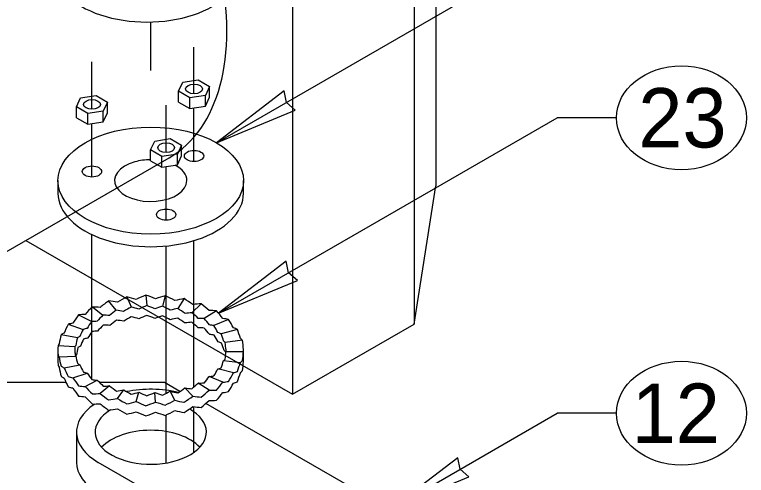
# Model space of a CAD drawing. Extents: x 99862 to 104211, y 98939 to 105076.
# Drawn here: x 101481.1 to 101678.3, y 101634.5 to 101758.7 of the extents above; entities that cross this region are included whole.
import ezdxf

# ---------------------------------------------------------------- set-up
doc = ezdxf.new("R2010")
doc.units = 0
for name, color, linetype in [('Level 11', 7, 'Continuous'), ('Level 12', 7, 'Continuous'), ('Level 15', 7, 'Continuous'), ('Level 2', 7, 'Continuous'), ('Level 20', 7, 'Continuous'), ('Level 24', 7, 'Continuous'), ('Level 26', 7, 'Continuous')]:
    doc.layers.add(name, color=color, linetype=linetype)

msp = doc.modelspace()

# ---------------------------------------------------------------- linework, layer by layer
at = {"layer": 'Level 11'}
for p, q in [((101525.26, 101738.07), (101526.38, 101740.49)), ((101526.38, 101740.49), (101530.56, 101741.13)), ((101530.56, 101741.13), (101533.62, 101739.37)), ((101525.26, 101735.16), (101525.26, 101738.07)), ((101528.32, 101736.31), (101525.26, 101738.07)), ((101533.62, 101739.37), (101532.5, 101736.95)), ((101533.62, 101736.46), (101533.62, 101739.37)), ((101497.75, 101733.87), (101498.87, 101736.28)), ((101498.87, 101736.28), (101503.05, 101736.93)), ((101503.05, 101736.93), (101506.11, 101735.16)), ((101532.5, 101736.95), (101528.32, 101736.31)), ((101528.32, 101733.4), (101528.32, 101736.31)), ((101532.5, 101734.04), (101532.5, 101736.95)), ((101532.5, 101734.04), (101533.62, 101736.46)), ((101497.75, 101730.96), (101497.75, 101733.87)), ((101500.81, 101732.1), (101497.75, 101733.87)), ((101506.11, 101735.16), (101504.99, 101732.75)), ((101506.11, 101732.25), (101506.11, 101735.16)), ((101525.26, 101735.16), (101528.32, 101733.4)), ((101528.32, 101733.4), (101532.5, 101734.04)), ((101504.99, 101732.75), (101500.81, 101732.1)), ((101500.81, 101729.19), (101500.81, 101732.1)), ((101504.99, 101729.84), (101504.99, 101732.75)), ((101504.99, 101729.84), (101506.11, 101732.25)), ((101497.75, 101730.96), (101500.81, 101729.19)), ((101500.81, 101729.19), (101504.99, 101729.84)), ((101517.73, 101722.26), (101518.86, 101724.67)), ((101518.86, 101724.67), (101523.04, 101725.32)), ((101523.04, 101725.32), (101526.1, 101723.55)), ((101517.73, 101719.35), (101517.73, 101722.26)), ((101520.8, 101720.49), (101517.73, 101722.26)), ((101526.1, 101723.55), (101524.98, 101721.14)), ((101526.1, 101720.64), (101526.1, 101723.55)), ((101524.98, 101721.14), (101520.8, 101720.49)), ((101520.8, 101717.58), (101520.8, 101720.49)), ((101524.98, 101718.23), (101524.98, 101721.14)), ((101524.98, 101718.23), (101526.1, 101720.64)), ((101517.73, 101719.35), (101520.8, 101717.58)), ((101520.8, 101717.58), (101524.98, 101718.23)), ((101492.77, 101713.99), (101492.77, 101710.59)), ((101542.77, 101710.59), (101542.77, 101713.99))]:
    msp.add_line(p, q, dxfattribs=at)
for centre, major_axis in [((101529.44, 101738.72), (2.27, 0)), ((101501.93, 101734.52), (2.27, 0)), ((101517.77, 101713.99), (-25, 0)), ((101521.92, 101722.9), (2.27, 0)), ((101529.44, 101720.64), (-2.6, 0)), ((101501.93, 101716.44), (-2.6, 0)), ((101521.92, 101704.83), (-2.6, 0))]:
    msp.add_ellipse(centre, major_axis=major_axis, ratio=0.57735, dxfattribs=at)
for centre, major_axis, start_param, end_param in [((101517.77, 101713.99), (9.74, 0), 2.024427, 6.283185), ((101517.77, 101713.99), (9.74, 0), 1.57464, 2.024427), ((101517.77, 101713.99), (9.74, 0), 0, 0.827732), ((101517.77, 101710.59), (-25, 0), 0, 3.141593)]:
    msp.add_ellipse(centre, major_axis=major_axis, ratio=0.57735, start_param=start_param, end_param=end_param, dxfattribs=at)
at = {"layer": 'Level 12'}
for p, q in [((101618.94, 101604.1), (101532.64, 101653.92)), ((101497.77, 101646.17), (101497.77, 101638.01)), ((101604.42, 101579.82), (101503.63, 101638.01))]:
    msp.add_line(p, q, dxfattribs=at)
for centre, major_axis, start_param, end_param in [((101517.77, 101646.17), (-20, 0), 4.329676, 5.04454), ((101517.77, 101646.17), (-20, 0), 5.567806, 7.068583), ((101517.77, 101646.17), (-15, 0), 5.520663, 10.229056), ((101517.77, 101638.01), (15, 0), 0.490883, 2.65071), ((101517.77, 101638.01), (20, 0), 3.141593, 3.926991)]:
    msp.add_ellipse(centre, major_axis=major_axis, ratio=0.57735, start_param=start_param, end_param=end_param, dxfattribs=at)
at = {"layer": 'Level 15'}
for p, q in [((101535.45, 101724.2), (101627.26, 101777.2)), ((101517.77, 101743.71), (101517.77, 101756.75)), ((101529.37, 101737.41), (101529.37, 101749.96)), ((101501.93, 101733.21), (101501.93, 101746.05)), ((101521.92, 101721.59), (101521.92, 101734.29)), ((101529.37, 101719.14), (101529.37, 101733.56)), ((101536.02, 101678.25), (101627.26, 101730.92)), ((101643.26, 101730.92), (101627.26, 101730.92)), ((101501.93, 101714.93), (101501.93, 101729.36)), ((101521.92, 101703.32), (101521.92, 101717.75)), ((101501.93, 101660.33), (101501.93, 101699.42)), ((101521.92, 101656.61), (101521.92, 101696.35)), ((101529.37, 101658.34), (101529.37, 101697.8)), ((101529.37, 101640.68), (101529.37, 101653.04)), ((101521.92, 101637.85), (101521.92, 101650.81)), ((101582.24, 101625.28), (101627.26, 101651.27)), ((101643.26, 101651.27), (101627.26, 101651.27))]:
    msp.add_line(p, q, dxfattribs=at)
for points in [[(101535.45, 101724.2), (101556.71, 101733.02), (101554.31, 101735.08), (101553.73, 101738.2)], [(101536.02, 101678.25), (101557.28, 101687.08), (101554.88, 101689.14), (101554.3, 101692.25)], [(101582.24, 101625.28), (101603.5, 101634.11), (101601.1, 101636.17), (101600.52, 101639.28)]]:
    msp.add_lwpolyline(points, close=True, dxfattribs=at)
at = {"layer": 'Level 2'}
msp.add_ellipse((101516.75, 101771.17), major_axis=(-25, 0), ratio=0.57735, start_param=0, end_param=3.141593, dxfattribs=at)
at = {"layer": 'Level 20'}
for centre in [(101660.76, 101730.92), (101660.76, 101651.27)]:
    msp.add_ellipse(centre, major_axis=(-17.5, 0), ratio=0.8, dxfattribs=at)
at = {"layer": 'Level 24'}
for p, q in [((101511.3, 101682.63), (101512.48, 101679.91)), ((101516.46, 101683.11), (101516.7, 101680.28)), ((101521.68, 101682.95), (101520.96, 101680.13)), ((101508.49, 101679.03), (101506.42, 101681.55)), ((101526.73, 101682.17), (101525.07, 101679.48)), ((101528.84, 101678.35), (101531.38, 101680.8)), ((101502.04, 101679.91), (101504.89, 101677.7)), ((101535.46, 101678.89), (101532.14, 101676.79)), ((101498.34, 101677.78), (101501.86, 101675.96)), ((101538.74, 101676.55), (101534.79, 101674.89)), ((101495.5, 101675.24), (101499.52, 101673.88)), ((101541.11, 101673.86), (101536.71, 101672.7)), ((101497.99, 101671.58), (101493.62, 101672.43)), ((101542.46, 101670.95), (101537.79, 101670.34)), ((101497.33, 101669.13), (101492.81, 101669.45)), ((101492.77, 101668.2), (101492.77, 101665.44)), ((101493.08, 101666.43), (101497.57, 101666.67)), ((101497.36, 101667.52), (101497.38, 101667.1)), ((101538.01, 101667.89), (101542.74, 101667.94)), ((101538.09, 101667.89), (101538.07, 101668.25)), ((101542.77, 101665.44), (101542.77, 101668.2)), ((101537.34, 101665.48), (101541.92, 101664.96)), ((101494.43, 101663.52), (101498.7, 101664.29)), ((101540.05, 101662.14), (101535.82, 101663.2)), ((101496.81, 101660.83), (101500.66, 101662.1)), ((101537.2, 101659.61), (101533.52, 101661.14)), ((101500.09, 101658.49), (101503.36, 101660.19)), ((101533.51, 101657.47), (101530.53, 101659.41)), ((101506.69, 101658.65), (101504.16, 101656.58)), ((101508.81, 101655.22), (101510.49, 101657.55)), ((101513.86, 101654.44), (101514.59, 101656.93)), ((101519.08, 101654.28), (101518.83, 101656.81)), ((101524.24, 101654.75), (101523.02, 101657.2)), ((101526.98, 101658.08), (101529.12, 101655.83))]:
    msp.add_line(p, q, dxfattribs=at)
for centre, major_axis, ratio, start_param, end_param in [((101517.77, 101667.71), (23.57, 14.17), 0.588004, 1.492908, 1.597627), ((101517.77, 101667.71), (-24.46, 11.73), 0.440657, 5.077658, 5.182378), ((101517.77, 101667.71), (23.99, 13.35), 0.527399, 1.337713, 1.442432), ((101517.77, 101667.71), (-24.17, 12.86), 0.497899, 4.918981, 5.0237), ((101517.77, 101667.71), (24.32, 12.32), 0.468967, 1.180574, 1.285294), ((101517.77, 101667.71), (-23.79, 13.78), 0.557438, 4.763018, 4.867737), ((101517.77, 101667.71), (23.09, 14.75), 0.650745, 1.648089, 1.752809), ((101517.77, 101667.71), (-24.67, 10.41), 0.386234, 5.240379, 5.345098), ((101517.77, 101667.71), (24.58, 11.09), 0.413044, 1.020027, 1.124747), ((101517.77, 101667.71), (-23.34, 14.49), 0.6191, 4.608118, 4.712837), ((101517.77, 101667.71), (24.76, 9.68), 0.360362, 0.8552, 0.959575), ((101517.77, 101667.71), (-22.85, 14.83), 0.683288, 4.448984, 4.554049), ((101517.77, 101667.71), (22.56, 15.04), 0.715795, 1.806331, 1.911051), ((101517.77, 101667.71), (-24.82, 8.91), 0.335596, 5.40825, 5.512969), ((101517.72, 101667.72), (-18.31, -12.12), 0.663313, 4.778515, 4.885072), ((101517.72, 101667.74), (20.54, -8.62), 0.376508, 2.084067, 2.18753), ((101517.72, 101667.71), (-18.71, -11.62), 0.598244, 4.622152, 4.729007), ((101517.72, 101667.75), (20.39, -9.75), 0.429328, 1.924562, 2.027518), ((101517.72, 101667.71), (-19.05, -10.93), 0.535491, 4.465396, 4.572456), ((101517.72, 101667.75), (20.16, -10.74), 0.484995, 1.769848, 1.872378), ((101517.72, 101667.71), (-19.34, -10.08), 0.475083, 4.306477, 4.413646), ((101517.72, 101667.75), (19.84, -11.56), 0.543025, 1.61865, 1.720863), ((101517.72, 101667.71), (-19.58, -9.08), 0.417364, 4.144071, 4.251256), ((101517.72, 101667.75), (19.43, -12.2), 0.603283, 1.46947, 1.571493), ((101517.77, 101667.71), (24.87, 8.06), 0.313871, 0.683714, 0.78878), ((101517.77, 101667.71), (-22.31, 15.05), 0.749264, 4.290148, 4.394522), ((101517.77, 101667.71), (22.09, 14.93), 0.783391, 1.973965, 2.078685), ((101517.77, 101667.71), (-24.91, 7.25), 0.290225, 5.582091, 5.686811), ((101517.72, 101667.72), (-17.89, -12.4), 0.730894, 4.937429, 5.043598), ((101517.72, 101667.74), (20.61, -7.34), 0.327453, 2.249442, 2.353465), ((101517.82, 101665.93), (-18.89, -11.29), 0.566582, 4.65521, 4.761435), ((101517.83, 101665.9), (20.47, -9.2), 0.402516, 1.905515, 2.007935), ((101517.82, 101665.93), (-19.21, -10.52), 0.50498, 4.498422, 4.604994), ((101517.83, 101665.89), (20.29, -10.27), 0.456845, 1.749535, 1.851681), ((101517.82, 101665.93), (-19.47, -9.6), 0.445851, 4.33846, 4.445308), ((101517.83, 101665.89), (20.01, -11.17), 0.51373, 1.59739, 1.699385), ((101517.82, 101665.94), (-19.68, -8.52), 0.389728, 4.174109, 4.281154), ((101517.83, 101665.89), (19.64, -11.91), 0.572873, 1.447674, 1.549653), ((101517.72, 101667.71), (-19.77, -7.94), 0.363082, 3.977435, 4.084195), ((101517.72, 101667.75), (18.96, -12.55), 0.66635, 1.317558, 1.419881), ((101517.72, 101667.71), (-19.92, -6.63), 0.315205, 3.804372, 3.911664), ((101517.72, 101667.75), (18.4, -12.84), 0.731211, 1.168256, 1.269974), ((101517.77, 101667.71), (24.94, 6.37), 0.270119, 0.507084, 0.611804), ((101517.77, 101667.71), (-21.94, 14.64), 0.818147, 4.112606, 4.217325), ((101517.77, 101667.71), (21.92, 14.08), 0.853385, 2.16914, 2.27386), ((101517.77, 101667.71), (-24.96, 5.45), 0.252109, 5.762237, 5.866957), ((101517.72, 101667.73), (-17.52, -12.37), 0.801277, 5.105481, 5.211183), ((101517.72, 101667.74), (20.62, -5.93), 0.283588, 2.42148, 2.526083), ((101517.82, 101665.92), (-18.1, -12.29), 0.696771, 4.966104, 5.071448), ((101517.83, 101665.9), (20.62, -6.65), 0.304762, 2.23369, 2.336945), ((101517.82, 101665.93), (-18.51, -11.89), 0.630481, 4.810354, 4.916165), ((101517.83, 101665.9), (20.58, -7.99), 0.351433, 2.06656, 2.169358), ((101517.82, 101665.94), (-19.85, -7.31), 0.337596, 4.00437, 4.11153), ((101517.83, 101665.89), (19.19, -12.45), 0.63428, 1.299034, 1.400798), ((101517.72, 101667.71), (-20.04, -5.26), 0.270295, 3.626269, 3.732988), ((101517.72, 101667.75), (17.89, -12.71), 0.799628, 1.006665, 1.108934), ((101517.77, 101667.71), (-24.99, 3.53), 0.223561, 5.948263, 6.052982), ((101517.72, 101667.73), (-17.45, -11.66), 0.874367, 5.304524, 5.409696), ((101517.72, 101667.73), (20.58, -4.42), 0.246838, 2.600485, 2.705657), ((101517.82, 101665.92), (-17.69, -12.44), 0.765721, 5.126739, 5.231572), ((101517.82, 101665.91), (20.61, -5.19), 0.264186, 2.407555, 2.51132), ((101517.82, 101665.93), (-19.98, -5.95), 0.29281, 3.828548, 3.936073), ((101517.83, 101665.89), (18.7, -12.68), 0.698549, 1.144423, 1.247134), ((101517.82, 101665.93), (-20.1, -4.52), 0.251785, 3.646437, 3.75321), ((101517.72, 101667.71), (-20.15, -3.75), 0.235717, 3.442095, 3.548503), ((101517.72, 101667.74), (17.65, -11.94), 0.871239, 0.815178, 0.917775), ((101517.77, 101667.71), (24.98, 4.51), 0.236491, 0.323887, 0.428607), ((101517.77, 101667.71), (-22.18, 12.98), 0.888613, 3.882951, 3.987671), ((101517.77, 101667.71), (22.99, 10.64), 0.922162, 2.476441, 2.581161), ((101517.72, 101667.74), (-18.93, -7.75), 0.945022, 5.676186, 5.780789), ((101517.72, 101667.73), (20.52, -2.82), 0.219467, 2.786003, 2.891705), ((101517.82, 101665.91), (-17.41, -12.14), 0.837545, 5.303627, 5.407926), ((101517.82, 101665.91), (20.55, -3.63), 0.231835, 2.588195, 2.692495), ((101517.83, 101665.89), (18.13, -12.83), 0.765007, 0.991605, 1.094336), ((101517.72, 101667.71), (-20.25, -2.16), 0.212017, 3.253154, 3.35918), ((101517.77, 101667.71), (24.99, 2.54), 0.213589, 0.135385, 0.240105), ((101517.77, 101667.71), (-24.57, 4.88), 0.947565, 3.380043, 3.484762), ((101517.77, 101667.71), (-24.57, 4.88), 0.947565, 0.13373, 0.23845), ((101517.77, 101667.71), (-25, 1.53), 0.206802, 6.138761, 6.243481), ((101517.72, 101667.74), (18.83, -8.32), 0.941831, 3.50935, 3.613372), ((101517.72, 101667.72), (20.44, -1.17), 0.203679, 2.976608, 3.082777), ((101517.82, 101665.91), (-17.81, -10.59), 0.911117, 5.546488, 5.650253), ((101517.82, 101665.92), (20.48, -2), 0.210005, 2.774764, 2.879597), ((101517.82, 101665.93), (-20.2, -2.97), 0.222374, 3.458633, 3.565603), ((101517.83, 101665.9), (17.71, -12.45), 0.835077, 0.818447, 0.921647), ((101517.72, 101667.74), (18.83, -8.32), 0.941831, 0.468891, 0.57191), ((101517.77, 101667.71), (25, 0.51), 0.203365, 3.189796, 3.294515), ((101517.72, 101667.72), (20.35, 0.51), 0.201051, 3.169927, 3.276484), ((101517.82, 101665.92), (20.39, -0.33), 0.200662, 2.965412, 3.034193), ((101517.72, 101667.74), (17.65, -11.94), 0.871239, 3.857172, 3.960635), ((101517.82, 101665.93), (-20.3, -1.34), 0.20486, 3.266696, 3.373414), ((101517.72, 101667.74), (-18.93, -7.75), 0.945022, 2.63741, 2.740916), ((101517.83, 101665.9), (17.89, -10.9), 0.907593, 0.67037, 0.687271), ((101517.72, 101667.72), (20.35, 0.51), 0.201051, 6.203047, 6.308631), ((101517.77, 101667.71), (22.99, 10.64), 0.922162, 5.722754, 5.827474), ((101517.77, 101667.71), (25, 0.51), 0.203365, 6.226668, 6.331388), ((101517.77, 101665.93), (-24.57, -4.88), 0.947565, 6.097095, 6.149455), ((101517.77, 101667.71), (-22.18, 12.98), 0.888613, 0.636639, 0.741359), ((101517.72, 101667.71), (-20.25, -2.16), 0.212017, 0.221451, 0.328307), ((101517.72, 101667.73), (-17.45, -11.66), 0.874367, 2.267499, 2.37153), ((101517.72, 101667.72), (20.44, -1.17), 0.203679, 6.011323, 6.116415), ((101517.77, 101667.71), (21.92, 14.08), 0.853385, 5.415452, 5.520172), ((101517.77, 101667.71), (-25, 1.53), 0.206802, 2.892449, 2.997168), ((101517.77, 101665.93), (-24.57, -4.88), 0.947565, 2.798423, 2.903143), ((101517.77, 101665.93), (25, -0.51), 0.203365, 6.234982, 6.287342), ((101517.77, 101665.93), (-25, -1.53), 0.206802, 0.039705, 0.144424), ((101517.77, 101665.93), (22.99, -10.64), 0.922162, 3.702024, 3.806744), ((101517.77, 101667.71), (24.99, 2.54), 0.213589, 3.381698, 3.486418), ((101517.77, 101667.71), (-21.94, 14.64), 0.818147, 0.866293, 0.971013), ((101517.72, 101667.75), (17.89, -12.71), 0.799628, 4.049974, 4.152929), ((101517.72, 101667.73), (-17.52, -12.37), 0.801277, 2.070195, 2.174763), ((101517.72, 101667.73), (20.52, -2.82), 0.219467, 5.822424, 5.926992), ((101517.77, 101665.93), (24.99, -2.54), 0.213589, 6.04308, 6.1478), ((101517.77, 101665.93), (-24.99, -3.53), 0.223561, 0.230203, 0.334923), ((101517.77, 101665.93), (21.92, -14.08), 0.853385, 4.009326, 4.114045), ((101517.77, 101667.71), (24.98, 4.51), 0.236491, 3.570199, 3.674919), ((101517.77, 101667.71), (-22.31, 15.05), 0.749264, 1.043836, 1.148555), ((101517.72, 101667.71), (-20.15, -3.75), 0.235717, 0.411581, 0.518641), ((101517.72, 101667.75), (18.4, -12.84), 0.731211, 4.212591, 4.315121), ((101517.72, 101667.72), (-17.89, -12.4), 0.730894, 1.903791, 2.008884), ((101517.72, 101667.73), (20.58, -4.42), 0.246838, 5.638651, 5.742681), ((101517.77, 101667.71), (22.09, 14.93), 0.783391, 5.220277, 5.324997), ((101517.77, 101667.71), (-24.99, 3.53), 0.223561, 2.70195, 2.80667), ((101517.77, 101665.93), (-22.18, -12.98), 0.888613, 2.295514, 2.400234), ((101517.72, 101667.71), (-20.04, -5.26), 0.270295, 0.596668, 0.703484), ((101517.72, 101667.75), (18.96, -12.55), 0.66635, 4.362228, 4.464795), ((101517.72, 101667.72), (-18.31, -12.12), 0.663313, 1.746368, 1.851952), ((101517.72, 101667.74), (20.62, -5.93), 0.283588, 5.461353, 5.564858), ((101517.77, 101667.71), (22.56, 15.04), 0.715795, 5.052644, 5.157364), ((101517.77, 101667.71), (-24.96, 5.45), 0.252109, 2.515925, 2.620645), ((101517.77, 101665.93), (-21.94, -14.64), 0.818147, 2.06586, 2.17058), ((101517.77, 101665.93), (24.98, -4.51), 0.236491, 5.854579, 5.959298), ((101517.77, 101665.93), (-24.96, -5.45), 0.252109, 0.416228, 0.520948), ((101517.77, 101665.93), (22.09, -14.93), 0.783391, 4.204501, 4.308875), ((101517.77, 101667.71), (24.94, 6.37), 0.270119, 3.753396, 3.857771), ((101517.77, 101667.71), (-22.85, 14.83), 0.683288, 1.202326, 1.307392), ((101517.72, 101667.71), (-19.92, -6.63), 0.315205, 0.775717, 0.883239), ((101517.72, 101667.75), (19.43, -12.2), 0.603283, 4.515147, 4.616833), ((101517.72, 101667.71), (-19.77, -7.94), 0.363082, 0.948373, 1.055486), ((101517.72, 101667.75), (19.84, -11.56), 0.543025, 4.663917, 4.765887), ((101517.72, 101667.71), (-19.58, -9.08), 0.417364, 1.115309, 1.222265), ((101517.72, 101667.75), (20.16, -10.74), 0.484995, 4.814659, 4.916713), ((101517.72, 101667.71), (-19.34, -10.08), 0.475083, 1.277326, 1.384046), ((101517.72, 101667.75), (20.39, -9.75), 0.429328, 4.968557, 5.070826), ((101517.72, 101667.71), (-19.05, -10.93), 0.535491, 1.435534, 1.541941), ((101517.72, 101667.74), (20.54, -8.62), 0.376508, 5.126927, 5.229524), ((101517.72, 101667.71), (-18.71, -11.62), 0.598244, 1.591279, 1.697305), ((101517.72, 101667.74), (20.61, -7.34), 0.327453, 5.290905, 5.393923), ((101517.77, 101667.71), (23.09, 14.75), 0.650745, 4.894402, 4.999121), ((101517.77, 101667.71), (-24.91, 7.25), 0.290225, 2.335779, 2.440499), ((101517.77, 101665.93), (-22.31, -15.05), 0.749264, 1.888318, 1.993037), ((101517.77, 101665.93), (24.94, -6.37), 0.270119, 5.671382, 5.776101), ((101517.77, 101665.93), (-24.91, -7.21), 0.292084, 0.595944, 0.70101), ((101517.77, 101665.93), (22.6, -14.92), 0.716006, 4.368664, 4.47373), ((101517.77, 101667.71), (24.87, 8.06), 0.313871, 3.930372, 4.035437), ((101517.77, 101667.71), (-23.34, 14.49), 0.6191, 1.362151, 1.466525), ((101517.77, 101667.71), (24.76, 9.68), 0.360362, 4.101167, 4.205887), ((101517.77, 101667.71), (-23.79, 13.78), 0.557438, 1.516705, 1.621425), ((101517.77, 101667.71), (23.99, 13.35), 0.527399, 4.584025, 4.688745), ((101517.77, 101667.71), (-24.67, 10.41), 0.386234, 1.994066, 2.098786), ((101517.77, 101667.71), (23.57, 14.17), 0.588004, 4.73922, 4.84394), ((101517.77, 101667.71), (-24.82, 8.91), 0.335596, 2.161937, 2.266657), ((101517.77, 101665.93), (24.87, -8.1), 0.312139, 5.494389, 5.599109), ((101517.77, 101665.93), (-24.82, -8.91), 0.335596, 0.770561, 0.874936), ((101517.77, 101665.93), (23.09, -14.75), 0.650745, 4.530376, 4.635096), ((101517.77, 101667.71), (24.58, 11.09), 0.413044, 4.266339, 4.371059), ((101517.77, 101667.71), (-24.17, 12.86), 0.497899, 1.672668, 1.777388), ((101517.77, 101667.71), (24.32, 12.32), 0.468967, 4.426886, 4.531606), ((101517.77, 101667.71), (-24.46, 11.73), 0.440657, 1.831346, 1.936066), ((101517.77, 101665.93), (-23.34, -14.49), 0.6191, 1.570348, 1.675068), ((101517.77, 101665.93), (24.76, -9.68), 0.360362, 5.323611, 5.42833), ((101517.77, 101665.93), (-22.83, -14.93), 0.682966, 1.726553, 1.831273), ((101517.77, 101665.93), (-24.67, -10.41), 0.386234, 0.938087, 1.042807), ((101517.77, 101665.93), (23.57, -14.17), 0.588004, 4.685558, 4.790278), ((101517.77, 101665.93), (-24.46, -11.73), 0.440657, 1.100807, 1.205527), ((101517.77, 101665.93), (23.99, -13.35), 0.527399, 4.840753, 4.945473), ((101517.77, 101665.93), (-24.17, -12.86), 0.497899, 1.259485, 1.364205), ((101517.77, 101665.93), (24.32, -12.32), 0.468967, 4.997892, 5.102611), ((101517.77, 101665.93), (-23.79, -13.78), 0.557438, 1.415448, 1.520168), ((101517.77, 101665.93), (24.58, -11.09), 0.413044, 5.158439, 5.263158)]:
    msp.add_ellipse(centre, major_axis=major_axis, ratio=ratio, start_param=start_param, end_param=end_param, dxfattribs=at)
at = {"layer": 'Level 26'}
for p, q in [((101594.59, 101882.14), (101594.59, 101712.58)), ((101588.71, 101844.85), (101588.71, 101675.29)), ((101555.95, 101825.93), (101555.95, 101656.37)), ((101437.88, 101671.16), (101522.74, 101720.15)), ((101588.71, 101675.29), (101594.59, 101712.58)), ((101484.1, 101697.85), (101555.95, 101656.37)), ((101555.95, 101656.37), (101588.71, 101675.29)), ((101494.94, 101659.55), (101443.58, 101659.55)), ((101521.47, 101659.55), (101503.96, 101659.55)), ((101525.64, 101657.15), (101521.47, 101659.55))]:
    msp.add_line(p, q, dxfattribs=at)
msp.add_ellipse((101485.24, 101785.11), major_axis=(37.5, -64.95), ratio=0.57735, start_param=0, end_param=3.141593, dxfattribs=at)

# ---------------------------------------------------------------- texts
at = {"layer": 'Level 20'}
for s, p in [('23', (101649.13, 101722.92)), ('12', (101647.32, 101643.27))]:
    msp.add_text(s, height=16, dxfattribs=at).set_placement(p)

doc.saveas('drawing.dxf')
